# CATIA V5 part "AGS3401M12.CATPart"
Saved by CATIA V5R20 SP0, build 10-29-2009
Part number: AGS3401M12
Definition: NONE
Nomenclature: AGS3401M12
Source: Unknown
Description: AGS3401M12
Bounding box of the stored display mesh (mm): x -20 to 35, y -12.5 to 12.5, z -10 to 10
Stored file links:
  C:\Users\Utente\Desktop\IO LAVORO\3D X SITO CF\X SITO\PLASTICA\AGS\AGS3401M12.CATPart
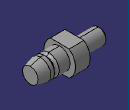
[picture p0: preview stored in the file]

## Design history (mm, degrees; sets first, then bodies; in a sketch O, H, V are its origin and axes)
Body1 "AGS3401M12" (main body)
  Solid1: solid without history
